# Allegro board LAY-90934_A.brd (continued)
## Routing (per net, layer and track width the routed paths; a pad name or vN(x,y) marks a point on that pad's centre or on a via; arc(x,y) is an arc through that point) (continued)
FT_NPWREN: length 2.2
  TOP w0.086: U28.60 3.46,31.02 TP136.1
FT_NSUSPEND: length 2.5
  TOP w0.086: U28.36 13.3,39.84 13.84,40.39 TP99.1
FT_ONOFF: length 7
  TOP w0.086: U13.12 46.33,71.1 46.48,71.25 46.48,72.64 46.8,72.96 48.58,72.96 v1(49.02,72.52)
  BOTTOM w0.086: U62.3 48.51,72.39 48.64,72.52 v1(49.02,72.52) R397.1
FT_OSCI: length 6.8
  TOP w0.086: U28.2 7.8,26.24 8.51,25.53 C128.1 9.02,24.26 9.02,22.23 8.04,21.25 X1.1
FT_OSCO: length 4.8
  TOP w0.086: X1.3 9.78,23.29 C134.1 8.3,26.25 U28.3
FT_POR_B: length 6.3
  TOP w0.086: U13.10 47.25,70.1 48.51,68.83 v1(48.51,67.5)
  BOTTOM w0.086: R417.1 48.26,67.25 v1(48.51,67.5) 48.51,67.5 U62.6
FT_RC_SEL: length 12.3
  TOP w0.086: R77.1 v1(38.29,67.56) ; U13.13 45.19,72.62 v1(45.21,72.64)
  BOTTOM w0.086: v1(38.29,67.56) 38.67,67.95 41.78,67.95 42.54,68.71 42.54,71.63 43.56,72.64 v1(45.21,72.64)
FT_SCL: length 111.8
  TOP w0.086: R227.2 v1(17.78,41.02) ; R255.1 v1(19.3,33.02) 18.67,33.02 18.17,33.52 U28.26 ; R155.1 v1(16,56.01) TP37.1 ; R164.2 v1(23.75,53.85) ; R45.1 v1(38.48,71.63) ; R159.2 v1(43.94,54.04)
  BOTTOM w0.086: R451.2 20.7,34.42 v1(19.3,33.02) 18.29,34.04 18.29,40.51 v1(17.78,41.02) 16.51,42.29 8.64,42.29 8,42.93 8,52.83 11.94,56.77 15.24,56.77 v1(16,56.01) 16.45,56.45 17.59,56.45 20.19,53.85 v1(23.75,53.85) 25.02,52.58 27.3,52.58 27.69,52.96 31.5,52.96 33.02,54.48 43.18,54.48 43.62,54.04 v1(43.94,54.04) 43.94,54.42 37.46,60.9 37.46,70.61 v1(38.48,71.63)
FT_SD_CD: length 127.7
  TOP w0.086: U13.16 43.69,76.32 v1(43.69,76.33)
  BOTTOM w0.086: U68.2 130.18,47.75 126.87,51.05 126.87,59.18 127.51,59.82 127.51,64.01 131.57,68.07 131.57,73.66 124.59,80.65 86.36,80.65 83.82,78.11 71.12,78.11 69.34,76.33 51.82,76.33 51.31,76.84 44.2,76.84 v1(43.69,76.33)
FT_SD_CD_EN: length 5.5
  TOP w0.086: R203.2 133.66,45.4 v1(134,45.4) U22.1
  BOTTOM w0.086: U68.4 133.84,48.4 134,48.25 134,45.77 134,45.77 v1(134,45.4)
FT_SD_PWR_EN: length 126.4
  TOP w0.086: v1(129.92,46.36) R202.2 R216.1 ; v1(51.18,74.3) v1(51.18,76.33)
  BOTTOM w0.086: U61.2 51.56,69.22 50.16,70.61 50.16,72.9 50.99,73.72 50.99,74.1 v1(51.18,74.3) ; v1(129.92,46.36) 128.08,48.2 128.08,49.47 126.62,50.93 126.62,59.31 127.25,59.94 127.25,64.14 131.32,68.2 131.32,73.53 124.46,80.39 86.49,80.39 83.95,77.85 71.25,77.85 69.47,76.07 51.43,76.07 v1(51.18,76.33)
FT_SD_PWREN: length 16.7
  TOP w0.086: v1(51.43,73.66) 51.24,73.47 44.89,73.47 44.19,72.77 U13.15
  BOTTOM w0.086: v1(51.43,73.66) 51.06,73.28 U61.6 51.06,70.74 51.69,70.1 52.2,70.1 52.77,69.53 52.77,66.99 R415.2
FT_SDA: length 111.8
  TOP w0.086: R160.2 44.7,54.48 44.7,54.48 v1(44.7,54.04) ; R156.1 v1(17.4,56.01) TP38.1 ; U28.27 18.39,34.02 18.67,34.29 ; 18.67,34.29 v1(19.3,34.29) R252.1 ; 18.67,34.29 18.44,34.52 U28.28 ; R51.1 v1(38.73,70.61) ; R228.2 v1(18.54,41.02) ; v1(23.75,53.21) 23.88,53.09 R170.2
  BOTTOM w0.086: R449.2 31.99,34.67 19.69,34.67 v1(19.3,34.29) 18.54,35.05 v1(18.54,41.02) 17.02,42.55 8.76,42.55 8.25,43.05 8.25,52.71 12.07,56.52 14.86,56.52 15.81,55.56 16.95,55.56 v1(17.4,56.01) 19.81,53.59 23.37,53.59 v1(23.75,53.21) 24.64,52.32 27.43,52.32 27.81,52.71 31.62,52.71 33.15,54.23 43.05,54.23 43.69,53.59 44.26,53.59 v1(44.7,54.04) 37.72,61.02 37.72,69.6 v1(38.73,70.61)
FT_SYS_NRST: length 4.8
  TOP w0.086: v1(46.99,72.52) 46.99,71.12 46.47,70.6 U13.11
  BOTTOM w0.086: R399.1 v1(46.99,72.52) 46.99,71.73 47.25,71.48 U62.1
FT_TEMP_NINT: length 2.5
  TOP w0.086: TP46.1 13.85,54.62 R154.2 15.5,54.1 U18.3
FT_TST0: length 29.6
  TOP w0.086: U28.21 10.77,31.02 6.98,34.8 6.98,36.45 2.79,40.64 2.79,49.28 v1(3.56,50.04) R178.1
FT_TST1: length 26.2
  TOP w0.086: R194.1 v1(3.56,47.24) 3.05,46.74 3.05,40.77 7.24,36.58 7.24,34.93 10.65,31.52 U28.22
FT_TST2: length 22.5
  TOP w0.086: R212.1 v1(3.56,44.45) 3.56,40.64 7.49,36.7 7.49,35.05 10.53,32.02 U28.23
FT_TST3: length 18.8
  TOP w0.086: U28.24 10.41,32.52 7.75,35.18 7.75,36.83 4.19,40.39 v1(4.19,41.53) R225.1
FT_USB_DN: length 29.8
  TOP w0.087: U54.C1 14.59,9.76 14.59,16.07 13.68,16.98 10.07,16.98 6.95,20.1 6.95,28.23 7.33,28.61 9.69,28.61 9.78,28.53 9.78,28.23 9.84,28.17 9.97,28.17 10.03,28.23 10.03,28.53 10.12,28.61 10.34,28.61 10.43,28.53 10.43,27.95 10.3,27.82 U28.7
FT_USB_DP: length 29.9
  TOP w0.087: U54.C2 14.37,9.76 14.37,15.98 13.59,16.76 9.98,16.76 6.73,20.01 6.73,28.32 7.24,28.83 10.43,28.83 10.64,28.62 10.64,27.98 10.8,27.82 U28.8
FTA_TCK: length 7.1
  TOP w0.086: v1(15.62,28.07) 14.99,28.07 14.8,27.88 U28.16
  BOTTOM w0.086: U65.2 19.79,29.57 18.29,28.07 v1(15.62,28.07)
FTA_TDI: length 4
  TOP w0.086: v1(17.91,28.83) 17.72,29.02 U28.17
  BOTTOM w0.086: v1(17.91,28.83) 18.67,28.83 19.81,29.97 U65.3
FTA_TDO: length 4.4
  TOP w0.086: U28.18 v1(18.67,29.52)
  BOTTOM w0.086: v1(18.67,29.52) 18.67,30.28 19.16,30.77 U65.5
FTA_TMS: length 3.6
  TOP w0.086: v1(19.43,30.37) 19.07,30.02 U28.19
  BOTTOM w0.086: v1(19.43,30.37) U65.4
FTC_RXD: length 78
  TOP w0.086: D16.C v1(11.3,39.88) 11.8,39.38 U28.39 ; v1(52.39,63.25) 51.75,63.88 49.28,63.88 49.02,64.14 42.93,64.14 38.86,60.07 37.72,60.07 35.69,62.1 v1(34.8,62.1)
  BOTTOM w0.086: v1(34.8,62.1) 34.54,61.85 26.92,61.85 22.61,57.53 11.56,57.53 6.98,52.96 6.98,42.42 8.89,40.51 10.67,40.51 v1(11.3,39.88) ; R409.1 57.4,65.66 54.61,65.66 52.39,63.44 v1(52.39,63.25)
FTC_TXD: length 78.6
  TOP w0.086: v1(35.18,61.6) 35.81,61.6 37.59,59.82 38.99,59.82 43.05,63.88 48.89,63.88 49.15,63.63 51.18,63.63 v1(52.2,62.61) ; D17.C v1(12.83,39.88) 12.3,39.35 U28.38
  BOTTOM w0.086: v1(12.83,39.88) 11.94,40.77 9.02,40.77 7.24,42.55 7.24,52.83 11.68,57.28 22.73,57.28 27.05,61.6 v1(35.18,61.6) ; R410.1 56.64,65.91 54.48,65.91 51.94,63.37 51.94,62.87 v1(52.2,62.61)
GPIO_IO00: length 57.3
  TOP w0.086: R49.2 124.59,71.51 124.59,72.14 v1(125.98,73.53) 126.24,73.53 127,74.3 J4.27 ; U1.B16 97.88,56.33 98.13,56.58 98.49,56.58 98.93,57.02 98.93,59.69 99.76,60.52 100.86,60.52 106.43,66.08 v1(106.43,71.31)
  BOTTOM w0.086: v1(106.43,71.31) 107.48,71.31 107.57,71.22 107.57,70.44 107.66,70.36 107.86,70.36 107.95,70.44 107.95,72.64 111,75.69 118.74,75.69 119.63,74.8 123.99,74.8 124.08,74.89 124.08,75.09 123.99,75.18 121.5,75.18 121.41,75.28 121.41,75.47 121.5,75.57 123.95,75.57 v1(125.98,73.53)
GPIO_IO01: length 57.1
  TOP w0.086: J4.28 127,80.14 125.73,78.87 v1(125.73,74.42) 124.07,72.77 R41.2 ; v1(106.68,71.88) 106.93,71.63 106.93,71.25 106.68,70.99 106.68,65.99 102.49,61.8 102.49,59.44 100.84,57.79 99.69,57.79 99.19,57.28 99.19,56.9 98.62,56.33 U1.B17
  BOTTOM w0.086: v1(106.68,71.88) 106.43,72.14 105.75,72.14 105.66,72.22 105.66,72.43 105.75,72.52 107.44,72.52 110.87,75.95 118.87,75.95 119.63,75.18 120.94,75.18 121.03,75.28 121.03,75.47 120.94,75.57 120.11,75.57 120.02,75.66 120.02,75.85 120.11,75.95 124.21,75.95 v1(125.73,74.42)
GPIO_IO02: length 56.6
  TOP w0.086: U1.C16 97.99,56.08 98.76,56.08 99.44,56.77 99.44,57.15 99.82,57.53 100.97,57.53 102.74,59.31 102.74,61.71 106.93,65.9 106.93,70.87 107.19,71.12 107.19,72.26 107.06,72.39 106.26,72.39 106.17,72.3 106.17,71.84 106.09,71.76 105.88,71.76 105.79,71.84 105.79,72.3 105.7,72.39 105.5,72.39 105.41,72.3 105.41,71.59 105.32,71.5 105.12,71.5 105.03,71.59 105.03,72.26 104.9,72.39 102.74,72.39 102.62,72.52 102.62,72.81 102.52,72.9 102.33,72.9 102.23,72.81 102.23,72.35 102.14,72.26 101.95,72.26 101.85,72.35 101.85,72.81 101.76,72.9 101.56,72.9 101.47,72.81 101.47,72.35 101.38,72.26 101.18,72.26 101.09,72.35 101.09,72.81 101,72.9 100.8,72.9 100.71,72.81 100.71,71.97 100.62,71.88 100.42,71.88 100.33,71.97 100.33,72.77 100.2,72.9 98.71,72.9 98.62,72.99 98.62,74.2 98.52,74.3 98.33,74.3 98.23,74.2 98.23,72.96 98.11,72.83 95.19,72.83 95,72.64 95,71.71 94.91,71.63 94.7,71.63 94.61,71.71 94.61,72.68 94.53,72.77 94.32,72.77 94.23,72.68 94.23,72.35 94.15,72.26 93.94,72.26 93.85,72.35 93.85,72.64 93.73,72.77 93.31,72.77 93.22,72.86 93.22,73.06 93.31,73.15 97.44,73.15 97.54,73.24 97.54,73.57 97.44,73.66 R23.2 96.52,73.67 J4.3
GPIO_IO03: length 57.6
  TOP w0.086: J4.5 99.06,78.36 99.19,78.49 99.99,78.49 100.08,78.57 100.08,78.78 99.99,78.87 98.38,78.87 98.3,78.95 98.3,79.16 98.38,79.25 99.99,79.25 100.08,79.33 100.08,83.31 99.95,83.44 99.66,83.44 99.57,83.53 99.57,83.73 99.66,83.82 101.13,83.82 101.22,83.73 101.22,83.53 101.13,83.44 100.58,83.44 100.46,83.31 100.46,74.3 100.33,74.17 99.19,74.17 99.06,74.04 99.06,73.67 R24.2 99.07,73.27 99.19,73.15 102.78,73.15 102.87,73.06 102.87,72.74 102.96,72.64 103.16,72.64 103.25,72.74 103.25,73.06 103.34,73.15 103.54,73.15 103.63,73.06 103.63,72.77 103.76,72.64 107.19,72.64 107.44,72.39 107.44,70.99 107.19,70.74 107.19,65.81 103,61.62 103,59.18 101.47,57.66 101.47,56.52 100.75,55.8 98.27,55.8 U1.C17
GPIO_IO04: length 61.6
  TOP w0.086: J4.7 101.6,74.42 101.73,74.3 v1(102.62,74.3) 102.74,74.3 104.14,72.9 107.31,72.9 107.7,72.52 107.7,70.87 107.44,70.61 107.44,65.72 103.25,61.53 103.25,59.06 101.73,57.53 101.73,56.39 100.92,55.58 97.99,55.58 U1.D16
  BOTTOM w0.086: v1(102.62,74.3) 102.23,74.68 81.41,74.68 80.9,74.17 77.98,74.17 77.6,73.79 75.06,73.79 R395.1
GPIO_IO05: length 54.3
  TOP w0.086: U1.D17 101.05,55.33 102.62,56.9 102.62,57.66 103.76,58.8 103.76,61.34 107.95,65.53 107.95,70.36 108.2,70.61 108.2,72.01 v1(108.46,72.26) ; v1(125.98,72.9) 126.87,73.79 127.89,73.79 128.02,73.91 128.02,74.46 128.1,74.55 128.31,74.55 128.4,74.46 128.4,73.91 128.52,73.79 129.41,73.79 129.54,73.91 129.54,76.39
  BOTTOM w0.086: v1(108.46,72.26) 108.46,72.77 111.12,75.44 118.62,75.44 119.51,74.55 123.83,74.55 123.95,74.42 123.95,73.91 124.21,73.66 125.38,73.66 125.48,73.57 125.48,73.37 125.38,73.28 124.04,73.28 123.95,73.19 123.95,72.99 124.04,72.9 v1(125.98,72.9)
GPIO_IO06: length 55.1
  TOP w0.086: U1.E16 97.99,55.08 101.18,55.08 102.87,56.77 102.87,57.53 104.01,58.67 104.01,61.23 108.2,65.42 108.2,70.23 108.46,70.49 108.46,71.25 v1(108.97,71.76) ; v1(126.75,72.77) 127.51,73.53 132.76,73.53 132.84,73.62 132.84,73.83 132.76,73.91 132.21,73.91 132.08,74.04 J4.31
  BOTTOM w0.086: v1(126.75,72.77) 126.43,72.45 124.02,72.45 123.44,73.03 123.44,74.17 123.32,74.3 119.38,74.3 118.49,75.18 111.25,75.18 108.97,72.9 v1(108.97,71.76)
GPIO_IO07: length 54.3
  TOP w0.086: J4.26 124.46,78.99 124.33,78.87 123.32,78.87 123.19,78.74 123.19,73.72 v1(122.94,73.47) ; v1(109.47,72.14) 109.47,71.63 108.71,70.87 108.71,70.36 108.46,70.1 108.46,65.33 104.27,61.14 104.27,58.55 103.12,57.4 103.12,56.64 101.31,54.83 U1.E17
  BOTTOM w0.086: v1(109.47,72.14) 109.47,73.03 111.38,74.93 118.36,74.93 119.25,74.04 122.46,74.04 122.55,73.95 122.55,73.75 122.46,73.66 119.98,73.66 119.89,73.57 119.89,73.37 119.98,73.28 122.75,73.28 v1(122.94,73.47)
GPIO_IO08: length 39.4
  TOP w0.086: v1(108.9,69.91) 108.71,69.72 108.71,65.24 104.52,61.05 104.52,58.23 v1(104.34,58.05) ; v2(96.73,51.83) U1.K14 ; U9.5 117.69,70.77 v1(117.98,70.49)
  BOTTOM w0.086: v1(117.98,70.49) 109.98,70.49 109.41,69.91 v1(108.9,69.91) ; v1(104.34,58.05) 105.28,57.11 105.28,52.58 104.14,51.44 97.13,51.44 v2(96.73,51.83)
GPIO_IO09: length 41.3
  TOP w0.086: U1.F16 97.99,54.58 101.45,54.58 104.77,57.91 104.77,60.96 108.97,65.15 108.97,69.34 109.35,69.72 109.35,70.42 v1(109.28,70.49) ; U9.7 117.8,71.57 v1(117.98,71.76)
  BOTTOM w0.086: v1(109.28,70.49) 109.54,70.74 117.51,70.74 117.6,70.83 117.6,71.03 117.51,71.12 115.03,71.12 114.94,71.21 114.94,71.41 115.03,71.5 116.33,71.5 116.46,71.63 116.46,72.3 116.55,72.39 116.75,72.39 116.84,72.3 116.84,71.59 116.93,71.5 117.13,71.5 117.22,71.59 117.22,72.3 117.31,72.39 117.52,72.39 117.6,72.3 117.6,71.88 117.73,71.76 v1(117.98,71.76)
GPIO_IO10: length 44.1
  TOP w0.086: U1.F17 101.58,54.33 105.03,57.79 105.03,60.87 109.22,65.06 109.22,65.7 109.31,65.79 109.9,65.79 109.98,65.87 109.98,66.08 109.9,66.17 109.31,66.17 109.22,66.26 109.22,66.46 109.31,66.55 109.89,66.55 109.98,66.64 109.98,66.84 109.89,66.93 109.31,66.93 109.22,67.02 109.22,67.22 109.31,67.31 109.89,67.31 109.98,67.4 109.98,67.6 109.89,67.69 109.31,67.69 109.22,67.78 109.22,67.98 109.31,68.07 109.89,68.07 109.98,68.16 109.98,68.36 109.89,68.45 109.31,68.45 109.22,68.54 109.22,68.74 109.31,68.83 109.89,68.83 109.98,68.93 109.98,69.09 109.6,69.47 109.6,70.1 109.98,70.49 v1(109.98,71.25) ; U9.10 116.28,72.59 v1(116.59,72.9)
  BOTTOM w0.086: v1(109.98,71.25) 110.11,71.37 110.11,71.8 110.2,71.88 110.4,71.88 110.49,71.8 110.49,71.08 110.58,70.99 110.78,70.99 110.87,71.08 110.87,72.56 110.96,72.64 111.17,72.64 111.25,72.56 111.25,71.12 111.38,70.99 114.49,70.99 114.62,71.12 114.62,71.76 114.74,71.88 115.99,71.88 116.08,71.97 116.08,73.28 116.2,73.41 116.46,73.41 116.59,73.28 v1(116.59,72.9)
GPIO_IO11: length 41.2
  TOP w0.086: U9.2 115.88,69.92 v1(115.95,69.85) ; U1.G16 97.99,54.08 101.71,54.08 105.28,57.66 105.28,60.78 110.24,65.74 110.24,69.79 v1(110.05,69.98)
  BOTTOM w0.086: v1(110.05,69.98) 110.36,69.66 110.36,68.93 110.45,68.83 110.65,68.83 110.74,68.93 110.74,70.14 110.84,70.23 111.03,70.23 111.12,70.14 111.12,68.93 111.22,68.83 111.41,68.83 111.51,68.93 111.51,70.14 111.6,70.23 111.8,70.23 111.89,70.14 111.89,68.93 111.98,68.83 112.18,68.83 112.27,68.93 112.27,70.14 112.36,70.23 112.56,70.23 112.65,70.14 112.65,68.93 112.74,68.83 112.94,68.83 113.03,68.93 113.03,70.14 113.12,70.23 113.32,70.23 113.41,70.14 113.41,69.43 113.5,69.34 115.44,69.34 v1(115.95,69.85)
GPIO_IO12: length 88.7
  TOP w0.086: v1(102.17,57.28) 102.17,57.59 103.5,58.93 103.5,61.47 107.7,65.66 107.7,70.49 107.95,70.74 107.95,72.64 v1(107.12,73.47) ; v1(130.05,74.04) 130.56,74.04 130.81,74.3 130.81,78.87 132.08,80.14 J4.32 ; v2(96.73,54.87) U1.F14
  BOTTOM w0.086: v1(102.17,57.28) 102.17,56.71 100.71,55.25 97.11,55.25 v2(96.73,54.87) ; R391.1 79.89,74.68 80.64,74.68 81.15,75.18 104.14,75.18 106.3,73.03 106.68,73.03 v1(107.12,73.47) 107.25,73.47 110.24,76.45 127.63,76.45 v1(130.05,74.04)
GPIO_IO13: length 93.7
  TOP w0.086: U1.G17 101.84,53.83 105.54,57.53 105.54,60.73 110.49,65.68 110.49,72.09 109.11,73.47 v1(107.82,73.47) ; J4.33 134.62,74.3 133.6,73.28 128.08,73.28 v1(127.89,73.09)
  BOTTOM w0.086: R393.1 77.34,74.94 77.85,74.42 80.77,74.42 81.28,74.93 104.01,74.93 106.17,72.77 107.12,72.77 v1(107.82,73.47) 110.55,76.2 124.97,76.2 126.75,74.42 126.75,73.41 127.06,73.09 v1(127.89,73.09)
GPIO_IO14: length 57.6
  TOP w0.086: J4.8 101.6,83.69 101.73,83.82 102.27,83.82 102.36,83.91 102.36,84.11 102.27,84.2 98.39,84.2 98.3,84.29 98.3,84.49 98.39,84.58 102.65,84.58 102.74,84.49 102.74,79.12 103,78.87 105.03,78.87 105.28,78.61 105.28,74.3 105.66,73.91 109.02,73.91 110.74,72.19 110.74,65.6 105.79,60.64 105.79,57.4 101.97,53.58 97.99,53.58 U1.H16
GPIO_IO15: length 57.7
  TOP w0.086: J4.10 104.14,83.31 104.01,83.44 103.21,83.44 103.12,83.53 103.12,83.73 103.21,83.82 105.83,83.82 105.92,83.91 105.92,84.11 105.83,84.2 103.22,84.2 103.12,84.29 103.12,84.49 103.22,84.58 106.17,84.58 106.3,84.46 106.3,83.57 106.17,83.44 105.66,83.44 105.54,83.31 105.54,79.25 105.66,79.12 106.34,79.12 106.43,79.03 106.43,78.83 106.34,78.74 105.62,78.74 105.54,78.65 105.54,74.42 105.79,74.17 109.12,74.17 111,72.29 111,65.51 106.05,60.55 106.05,57.28 102.1,53.33 U1.H17
GPIO_IO16: length 46.4
  TOP w0.086: U1.J16 97.99,53.08 102.23,53.08 106.3,57.15 106.3,60.46 111.25,65.42 111.25,73.34 v1(111.38,73.47)
  BOTTOM w0.086: U59.16 127.16,71.21 126.94,71.44 120.33,71.44 117.86,73.91 115.06,73.91 114.43,73.28 111.57,73.28 v1(111.38,73.47)
GPIO_IO17: length 59.4
  TOP w0.086: J4.11 106.68,77.6 107.95,78.87 107.95,83.69 108.2,83.95 112.52,83.95 112.78,83.69 112.78,73.5 112.68,73.41 112.49,73.41 112.39,73.31 112.39,73.12 112.49,73.03 112.81,73.03 112.9,72.93 112.9,72.74 112.81,72.64 112.49,72.64 112.39,72.55 112.39,72.35 112.49,72.26 112.81,72.26 112.9,72.17 112.9,71.97 112.81,71.88 112.49,71.88 112.39,71.79 112.39,71.59 112.49,71.5 112.81,71.5 112.9,71.41 112.9,71.21 112.81,71.12 112.23,71.12 112.14,71.03 112.14,70.83 112.23,70.74 112.81,70.74 112.9,70.65 112.9,70.45 112.81,70.36 111.85,70.36 111.76,70.27 111.76,70.07 111.85,69.98 112.56,69.98 112.65,69.89 112.65,69.68 112.57,69.6 111.85,69.6 111.76,69.5 111.76,65.24 106.81,60.29 106.81,56.9 102.49,52.58 97.48,52.58 U1.K15
GPIO_IO18: length 70.6
  TOP w0.086: v1(105.79,55.25) 107.06,56.52 107.06,60.2 112.01,65.15 112.01,68.64 113.16,69.79 113.16,73.47 v1(113.41,73.72) 113.16,73.98 113.16,84.07 112.9,84.33 106.93,84.33 106.68,84.07 J4.12 ; v2(96.73,50.87) U1.M14
  BOTTOM w0.086: v1(105.79,55.25) 105.54,54.99 105.54,52.45 104.27,51.18 97.01,51.18 96.73,50.9 v2(96.73,50.87) ; v1(113.41,73.72) 113.86,74.17 117.98,74.17 119.63,72.52 122.81,72.52 123.63,71.69 128.03,71.69 128.18,71.54 U59.1
GPIO_IO19: length 60.2
  TOP w0.086: v1(129.67,72.26) 130.18,72.77 135.64,72.77 137.16,74.3 J4.35 ; U1.J17 102.36,52.83 106.55,57.02 106.55,60.38 111.51,65.33 111.51,70.74 112.14,71.37 v1(112.14,74.04)
  BOTTOM w0.086: v1(112.14,74.04) 112.78,74.68 118.24,74.68 119.89,73.03 123.06,73.03 123.89,72.2 127.57,72.2 128.27,72.9 129.03,72.9 v1(129.67,72.26) 129.38,71.97 U59.4
GPIO_IO20: length 68.9
  TOP w0.086: U1.K16 97.99,52.08 102.75,52.08 104.9,54.23 105.79,54.23 107.57,56.01 107.57,60.02 112.52,64.97 112.52,68.39 113.66,69.53 113.66,72.39 115.7,74.42 115.7,83.31 116.46,84.07 139.06,84.07 139.7,83.44 J4.38
GPIO_IO21: length 71
  TOP w0.086: U1.K17 102.62,52.33 104.77,54.48 105.66,54.48 107.31,56.13 107.31,60.11 112.27,65.06 112.27,68.52 113.41,69.66 113.41,72.52 115.44,74.55 115.44,83.44 116.33,84.33 141.35,84.33 142.24,83.44 J4.40
HP_J_L: length 7.4
  TOP w0.254: J10.4 v1(104.93,12.85) 105.32,13.25 TVS2.2 ; TP162.1 TVS2.2 ; TVS2.2 105.32,15.8 C171.1 R335.2
HP_J_R: length 7.4
  TOP w0.254: TVS1.2 TP163.1 ; TVS1.2 111.59,13.12 v1(111.93,12.79) J10.3 ; TVS1.2 111.59,15.8 C172.2 R336.2
I2C1_SCL: length 121.4
  TOP w0.086: TP168.1 66.42,13.34 v1(66.93,13.34) R366.2 ; R94.2 102.87,65.15 v1(102.62,64.9) ; R122.1 v1(112.71,60.2) ; v1(114.43,49.91) 116.08,49.91 119.06,46.93 119.06,38.8 120.84,37.02 120.84,28 122.81,26.04 122.81,23.37 122.93,23.25 R292.2 122.83,22.76 v1(122.83,22.73) U41.8
  BOTTOM w0.086: v1(122.83,22.73) 122.45,23.11 121.41,23.11 120.02,21.72 81.91,21.72 76.96,16.76 69.72,16.76 67.44,14.48 67.44,13.84 v1(66.93,13.34) ; R419.1 102.87,65.15 v1(102.62,64.9) 105.92,61.6 112.14,61.6 112.71,61.02 v1(112.71,60.2) 112.9,60.01 112.9,51.82 114.43,50.29 v1(114.43,49.91)
I2C1_SCL_1V8: length 4.5
  TOP w0.086: U41.4 v1(122.83,19.66) R327.2 122.93,19.17 122.81,19.05 122.81,17.39 R347.2
I2C1_SDA: length 123.3
  TOP w0.086: R130.1 v1(112.46,58.93) ; TP164.1 v1(66.93,14.35) R363.2 ; U41.7 123.23,22.14 v1(123.83,22.73) 123.83,22.74 R293.2 123.95,23.25 123.83,23.37 123.83,25.4 121.16,28.07 121.16,37.21 119.38,38.99 119.38,47.12 116.14,50.36 114.05,50.36 v1(113.86,50.17) ; v1(101.85,64.77) R93.2
  BOTTOM w0.086: v1(123.83,22.73) 123.13,23.43 121.22,23.43 119.76,21.97 81.79,21.97 76.83,17.02 69.6,17.02 v1(66.93,14.35) ; v1(113.86,50.17) 112.65,51.37 112.65,58.74 v1(112.46,58.93) 112.27,59.12 112.27,61.09 112.01,61.34 105.28,61.34 v1(101.85,64.77) R420.1
I2C1_SDA_1V8: length 4.8
  TOP w0.086: R348.2 123.83,17.39 123.83,19.05 123.95,19.17 R328.2 v1(123.82,19.68) 123.23,20.28 U41.5
I2C2_SCL: length 110.3
  TOP w0.086: U1.A11 95.23,59.04 96.39,60.2 96.39,60.96 100.08,64.64 v1(100.08,64.9) 100.08,65.67 R87.2 ; R121.1 v1(108.33,60.2) ; v1(67.82,42.8) 67.18,43.43 67.18,56.13 65.66,57.66 56.26,57.66 54.1,55.5 50.93,55.5 TP42.1 49.91,54.48 R169.1
  BOTTOM w0.086: v1(67.82,42.8) 82.8,42.8 83.19,43.18 89.28,43.18 90.74,44.64 97.98,44.64 98.68,43.94 101.47,43.94 108.58,51.05 108.58,57.79 107.82,58.55 107.82,59.69 v1(108.33,60.2) 108.08,60.45 105.16,60.45 100.71,64.9 v1(100.08,64.9)
I2C2_SDA: length 113.4
  TOP w0.086: v1(68.58,42.29) 68.58,42.67 67.44,43.82 67.44,56.26 65.79,57.91 56.13,57.91 53.97,55.75 49.53,55.75 TP41.1 48.89,55.12 R168.1 ; U1.B11 95.49,56.58 95.49,58.91 96.65,60.07 96.65,60.83 100.58,64.77 v1(100.58,65.41) R88.2 ; R129.1 v1(108.33,58.93)
  BOTTOM w0.086: v1(68.58,42.29) 68.83,42.55 82.93,42.55 83.31,42.93 89.41,42.93 90.87,44.39 97.85,44.39 98.55,43.69 101.6,43.69 108.84,50.93 108.84,58.42 v1(108.33,58.93) 108.84,59.44 108.84,60.33 108.46,60.71 105.28,60.71 v1(100.58,65.41)
I2C3_SCL: length 1.3
  TOP w0.086: R41.1 v1(122.68,72.01) R40.2
I2C3_SDA: length 1.3
  TOP w0.086: R48.2 v1(122.68,70.99) R49.1
I2C4_SCL: length 39.6
  TOP w0.086: R25.2 v1(100.46,73.66) R24.1 ; R28.1 v1(64.26,72.26)
  BOTTOM w0.086: v1(100.46,73.66) 99.69,74.42 85.22,74.42 83.95,73.15 78.87,73.15 78.49,73.53 65.53,73.53 v1(64.26,72.26)
I2C4_SDA: length 30.8
  TOP w0.086: R23.1 v1(95.12,73.66) R22.2 ; v1(67.56,72.26) R31.1
  BOTTOM w0.086: v1(67.56,72.26) 68.58,73.28 78.36,73.28 78.74,72.9 84.07,72.9 85.34,74.17 94.61,74.17 v1(95.12,73.66)
I2C/I3C1_SCL: length 16.2
  TOP w0.086: v1(102.87,67.28) 102.46,67.69 101.66,67.69 101.09,67.12 101.09,64.9 96.9,60.71 96.9,59.94 95.73,58.78 U1.A12
  BOTTOM w0.086: R419.2 v1(102.87,67.28) R406.2
I2C/I3C1_SDA: length 15
  TOP w0.086: v1(101.85,67.28) 101.35,66.78 101.35,64.77 97.16,60.58 97.16,59.82 95.99,58.65 95.99,56.58 U1.B12
  BOTTOM w0.086: R407.2 v1(101.85,67.28) R420.2
I3C1_SCL: length 3.7
  TOP w0.086: TP17.1 v1(102.49,69.72) 102.23,69.98 U11.B2
  BOTTOM w0.086: R405.2 102.87,68.96 R406.1 102.87,69.34 v1(102.49,69.72)
I3C1_SDA: length 3.2
  TOP w0.086: TP16.1 v1(101.85,69.79) 101.83,69.81 U11.C2
  BOTTOM w0.086: v1(101.85,69.79) R407.1 101.85,68.96 R408.2
I.MX_SPI_CLK: length 2.5
  TOP w0.086: R351.2 v1(129.29,17.4) 129.79,17.9 U43.3
I.MX_SPI_CS: length 12.1
  TOP w0.086: v1(127.76,17.78) 129.16,17.78 129.39,18.02 U43.2 ; R324.2 v1(119.63,19.17)
  BOTTOM w0.086: v1(127.76,17.78) 126.62,18.92 119.88,18.92 v1(119.63,19.17)
I.MX_SPI_MISO: length 2.3
  TOP w0.086: R352.2 130.19,17.29 v1(130.19,18.25) U43.4
I.MX_SPI_MOSI: length 2.2
  TOP w0.086: R353.2 v1(130.81,17.46) 130.59,17.68 U43.5
ILIM_5V_VBUS: length 3.5
  TOP w0.086: U48.6 33.04,14.84 33.15,14.73 33.15,12.45 TP171.1
IOEXP_IO24: length 49.1
  TOP w0.086: J4.18 v1(114.3,83.57) ; R144.2 123.32,57.15 128.14,61.98 128.14,62.42 v1(128.59,62.87)
  BOTTOM w0.086: v1(128.59,62.87) 129.67,62.87 132.72,65.91 132.72,74.17 123.83,83.06 114.81,83.06 v1(114.3,83.57)
IOEXP_IO25: length 46.1
  TOP w0.086: R143.2 119.89,56.52 120.52,56.52 120.9,56.9 123.44,56.9 128.59,62.04 v1(128.59,62.23) ; J4.22 v1(119.38,83.57)
  BOTTOM w0.086: v1(119.38,83.57) 123.7,83.57 132.97,74.3 132.97,65.79 129.41,62.23 v1(128.59,62.23)
IOEXP_IO27: length 36
  TOP w0.086: v1(127.13,64.64) 127.13,61.34 124.71,58.93 R131.2 ; v1(110.74,73.15) 110.49,73.15 109.22,74.42 J4.13
  BOTTOM w0.086: v1(110.74,73.15) 110.87,73.03 114.55,73.03 115.19,73.66 117.73,73.66 120.9,70.49 123.32,70.49 123.57,70.74 124.33,70.74 126.75,68.33 126.75,65.02 v1(127.13,64.64)
JTAG_TCK: length 21.9
  TOP w0.086: U1.U3 91.23,46.97 88.39,44.13 88.39,43.56 TP88.1 R229.1 88.39,42.03 88.27,41.91 88.27,40.51 84.2,36.45 84.2,35.31 82.42,33.53 81.28,33.53 81.08,33.73 U27.2
JTAG_TDI: length 21
  TOP w0.086: U27.5 83.35,34.83 83.95,35.43 83.95,36.55 87.5,40.11 TP96.1 88.01,41.78 88.01,44.13 90.8,46.93 v1(90.8,47.43) ; v2(93.19,50.32) 93.21,50.33 U1.P8
  BOTTOM w0.086: v2(93.19,50.32) 93.18,50.31 93.18,50.27 92.84,49.92 92.84,49.47 v1(90.8,47.43)
JTAG_TDO: length 18.7
  TOP w0.086: U27.10 81.48,36.65 82.04,37.21 83.9,37.21 86.74,40.06 86.74,42.67 TP86.1 86.3,43.18 89.66,46.55 89.66,47.31 90.99,48.63 90.99,49.08 U1.T3
JTAG_TMS: length 19.8
  TOP w0.086: v1(90.17,47.24) 90.17,46.67 87.5,44.01 TP87.1 86.99,42.67 86.99,39.95 83.69,36.65 83.69,35.81 83.51,35.63 U27.7 ; v2(92.25,50.32) 92.26,50.33 U1.P6
  BOTTOM w0.086: v2(92.25,50.32) 91.82,49.89 91.82,49.02 90.17,47.37 v1(90.17,47.24)
JTG_TCK: length 66.7
  TOP w0.086: J7.4 v1(76.71,31.24) 76.71,32.51 78.11,33.91 80.14,33.91 80.68,34.45 U27.1
  BOTTOM w0.086: v1(76.71,31.24) 76.2,30.73 75.18,30.73 74.93,30.99 67.94,30.99 63.37,26.42 51.43,26.42 50.29,27.56 24.64,27.56 22.63,29.57 U65.10
JTG_TDI: length 69.2
  TOP w0.086: J7.8 v1(79.25,31.5) 79.25,32.13 79.24,32.13 R258.2 ; v1(82.17,33.93) 81.88,34.22 U27.4
  BOTTOM w0.086: U65.9 22.61,29.97 24.77,27.81 50.42,27.81 51.56,26.67 63.25,26.67 67.82,31.24 75.06,31.24 75.31,30.99 75.82,30.99 76.83,32 78.74,32 v1(79.25,31.5) 81.28,33.53 81.76,33.53 v1(82.17,33.93)
JTG_TDO: length 79.1
  TOP w0.086: J7.6 77.98,27.81 77.72,27.56 76.33,27.56 76.07,27.81 v1(76.07,32.51) 76.07,36.45 78.74,39.12 80.26,39.12 81.08,38.3 U27.11
  BOTTOM w0.086: U65.7 22.57,30.77 25.02,28.32 50.67,28.32 51.82,27.18 62.99,27.18 68.33,32.51 v1(76.07,32.51)
JTG_TMS: length 70.6
  TOP w0.086: v1(83.19,36.45) 82.77,36.03 U27.8 ; 75.44,29.46 v1(75.44,31.5) 75.44,31.87 75.43,31.88 R257.2
  BOTTOM w0.086: v1(83.19,36.45) 78.99,32.26 76.71,32.26 75.95,31.5 v1(75.44,31.5) 67.69,31.5 63.12,26.92 51.69,26.92 50.55,28.07 24.89,28.07 22.59,30.37 U65.8
LD_I2C_SCL: length 16.7
  TOP w0.086: U47.B1 v1(22.48,15.46) ; v1(33.66,12.95) R368.1
  BOTTOM w0.086: v1(22.48,15.46) 22.48,14.86 26.04,11.3 32,11.3 v1(33.66,12.95)
LD_I2C_SDA: length 20
  TOP w0.086: U47.C1 v1(21.34,15.86) ; R364.1 v1(33.66,13.97)
  BOTTOM w0.086: v1(21.34,15.86) 21.49,16.01 R475.1 21.97,14.99 25.91,11.05 33.66,11.05 34.16,11.56 34.16,13.46 v1(33.66,13.97)
LD_NFLT: length 3
  TOP w0.086: U48.11 31.5,17.79 R330.2 R329.1
LD_NINT: length 12.7
  TOP w0.086: R329.2 v1(30.99,19.69) ; U47.D1 v1(24.26,16.26)
  BOTTOM w0.086: v1(30.99,19.69) 27.69,19.69 v1(24.26,16.26)
LED_B: length 1.2
  BOTTOM w0.381: Q11.3 R388.2
LED_G: length 1.2
  BOTTOM w0.381: Q13.3 R390.2
LED_R: length 1.2
  BOTTOM w0.381: Q12.3 R389.2
LINE_L: length 8.9
  TOP w0.254: U40.1 112.77,19.31 v1(112.78,19.3) C166.1 ; R335.1 v1(107.57,17.4)
  BOTTOM w0.254: v1(107.57,17.4) 110.87,17.4 v1(112.78,19.3)
LINE_R: length 9.4
  TOP w0.254: R336.1 v1(110.09,18.27) ; C165.1 v1(104.14,19.3) 104.15,19.31 U40.16
  BOTTOM w0.254: v1(110.09,18.27) 109.06,19.3 v1(104.14,19.3)
LINEVDD: length 4
  TOP w0.254: U40.6 110.66,22.57 v1(109.98,23.24)
  BOTTOM w0.381: v1(109.98,23.24) C305.1 109.19,24.3 L18.1
LPD4_VDD1: length 98.6
  TOP w0.203: R181.1 v1(20.45,51.18)
  TOP w0.254: U2.T9 74.36,48.98 v2(74.36,48.91) ; v2(80.21,48.91) 80.21,48.98 U2.G9 ; v2(80.42,46.36) 80.54,46.47 U2.F12 ; U2.G4 80.24,53.66 v2(80.24,53.72) ; U2.U1 73.06,56.03 v2(73.06,56.11) ; U2.T4 73.71,53.63 v2(73.71,53.71) ; v2(73.71,46.51) 73.71,46.58 U2.U12 ; U2.F1 80.54,56.24 v2(80.51,56.26)
  L3_PWR w0.508: v1(63.63,44.96) 57.91,44.96 56.9,43.94 56.9,41.4 56.39,40.89 53.4,40.89 52.39,39.88 38.1,39.88 37.59,39.37 v1(35.05,39.37)
  BOTTOM w0.203: v1(36.32,41.02) 36.2,41.15 29.97,41.15 27.43,43.69 27.43,46.36 23.37,50.42 21.21,50.42 v1(20.45,51.18)
  BOTTOM w0.254: v2(80.42,46.36) 80.21,46.57 v2(80.21,48.91) 80.77,49.47 80.77,53.19 v2(80.24,53.72) 80.28,53.76 C205.1 80.28,54.62 80.89,55.23 C203.1 80.89,55.89 v2(80.51,56.26) ; C204.1 73.14,56.19 v2(73.06,56.11) 74.17,55 74.17,54.16 v2(73.71,53.71) 74.17,53.25 74.17,52.45 73.67,51.96 C209.1 ; C209.1 73.67,46.55 v2(73.71,46.51) ; C209.1 74.35,48.9 v2(74.36,48.91)
  BOTTOM w0.381: C202.1 73.78,46.44 v2(73.71,46.51) ; v2(80.42,46.36) 80.42,45.75 C201.1 79.83,45.15 75.25,45.15
  BOTTOM w0.508: 73.53,44.96 v1(63.63,44.96)
LPD4_VDD2: length 63.5
  TOP w0.203: R148.1 v1(52.07,56.77) ; R166.1 v1(46.61,52.53)
  TOP w0.254: U2.N12 76.31,46.58 v2(76.31,46.51) ; v2(80.21,50.51) 80.21,50.43 U2.F8 ; v2(70.46,54.51) 70.46,54.43 U2.AA3 ; U2.U5 73.07,52.19 73.07,52.17 73.06,52.17 v2(73.06,52.11) ; v2(82.81,48.91) 82.81,48.83 U2.B10 ; v2(70.46,52.11) 70.46,52.17 70.47,52.17 70.47,52.19 U2.AA5 ; v2(75.01,46.51) 75.01,46.58 U2.R12 ; U2.B5 83.46,52.18 v2(83.46,52.11) ; v2(80.21,52.17) 80.22,52.17 80.22,52.19 U2.F5 ; v2(71.76,52.11) 71.76,52.17 71.77,52.17 71.77,52.19 U2.W5 ; U2.AB4 69.82,52.99 69.82,52.97 69.81,52.97 v2(69.81,52.91) ; v2(82.81,53.71) 82.81,53.78 U2.B3 ; U2.K10 77.61,48.83 v2(77.61,48.91) ; v2(82.16,56.11) 82.16,56.03 U2.D1 ; v2(75.66,56.11) 75.66,56.03 U2.N1 ; U2.R8 75.01,50.43 v2(75.01,50.51) ; v2(77.61,46.51) 77.61,46.57 77.62,46.57 77.62,46.59 U2.K12 ; U2.R1 74.69,56.04 v2(74.8,56.16) ; U2.AA10 70.47,48.19 70.47,48.17 70.46,48.17 v2(70.46,48.11) ; U2.U8 73.06,50.43 v2(73.06,50.51) ; U2.D12 82.16,46.58 v2(82.16,46.51) ; v2(74.93,52.01) 74.69,52.25 U2.R5 ; U2.AB9 69.81,49.63 v2(69.81,49.71) ; v2(73.06,48.11) 73.06,48.17 73.07,48.17 73.07,48.19 U2.U10 ; v2(71.76,50.51) 71.76,50.43 U2.W8 ; U2.H5 79.56,52.83 v2(79.56,52.91) ; v2(78.91,46.51) 78.91,46.57 78.92,46.57 78.92,46.59 U2.H12 ; U2.H1 79.24,56.24 v2(79.26,56.26) ; U2.AA8 70.46,50.43 v2(70.46,50.51) ; v2(73.06,54.51) 73.06,54.43 U2.U3 ; U2.A4 v2(84.33,53.31) ; v2(82.16,52.19) U2.D5 ; U2.F10 80.86,48.83 v2(80.86,48.91) ; U2.W1 71.76,56.03 v2(71.76,56.11) ; U2.N10 76.31,48.18 v2(76.31,48.11) ; U2.H8 79.24,50.56 v2(79.12,50.67) ; U2.N3 75.66,54.43 v2(75.66,54.51) ; v2(71.76,46.51) 71.76,46.57 71.77,46.57 71.77,46.59 U2.W12 ; U2.A9 v2(84.33,49.31) ; v2(77.69,54.48) 77.69,54.35 U2.K3 ; U2.D8 82.16,50.43 v2(82.16,50.51) ; U2.F3 80.86,54.43 v2(80.86,54.51) ; v2(83.46,50.51) 83.46,50.43 U2.B8 ; v2(77.62,56.03) U2.K1
  BOTTOM w0.203: v1(60.2,53.47) 58.67,51.94 47.12,51.94 46.61,52.45 v1(46.61,52.53) ; v1(52.07,56.77) 52.07,56.39 53.59,54.86 60.13,54.86 61.59,53.4 61.59,52.32 v1(61.72,52.2)
  BOTTOM w0.254: v2(82.16,52.19) 82.13,52.19 81.74,52.58 C221.1 ; R210.1 79.38,56.12 79.26,56.24 v2(79.26,56.26) ; v2(83.46,50.51) 83.55,50.6 R211.2 ; R209.1 83.55,52.02 v2(83.46,52.11) ; v2(76.31,46.51) 76.34,46.48 C212.1 ; v2(82.16,46.51) 82.25,46.6 C216.1 ; C208.1 84.18,49.16 v2(84.33,49.31) ; v2(70.46,50.51) 70.47,50.52 C220.1 ; C218.1 82.38,55.89 v2(82.16,56.11) ; v2(74.93,52.01) 74.66,52.27 C210.1 ; C214.1 84.18,53.45 v2(84.33,53.31) ; v2(92.26,54.81) 92.43,54.81 C153.1 ; v2(70.46,54.51) 70.37,54.6 C219.1 ; C211.1 v2(77.61,48.91) ; v2(82.16,50.51) 82.08,50.51 C217.1 ; v2(71.76,46.51) 71.77,46.5 C222.1 ; C213.1 74.94,50.58 v2(75.01,50.51)
  BOTTOM w0.381: C206.1 75.68,54.49 v2(75.66,54.51) ; C215.1 71.88,56.22 v2(71.76,56.11) ; v2(75.66,56.11) 75.56,56.21 C207.1
  vias: v1(63.88,54.86) v1(63.88,53.47) v1(63.88,52.2) v1(64.52,54.23) v1(64.52,52.83) v1(65.15,54.86) v1(65.15,53.47) v1(65.15,52.2) v2(91.74,50.83) v2(92.26,53.83) v2(92.26,52.83) v2(92.24,51.82) v2(92.26,50.84)
LPD4_VDD2_1V1: length 20.5
  TOP w0.203: R167.1 v1(47.62,52.53) ; v1(51.69,48.13) 51.69,46.48 51.08,45.87 U23.10
  BOTTOM w0.203: v1(47.62,52.53) 47.83,52.32 58.42,52.32 59.18,53.09 v1(59.18,53.47)
  BOTTOM w0.254: v1(56.26,47.37) 54.86,47.37 54.1,48.13 v1(51.69,48.13)
LPD4_VDD2_SW: length 3.5
  TOP w0.254: U19.5 54.95,48.66 v1(54.93,48.64) 54.28,48.64 TP71.1
  BOTTOM w0.254: R435.2 54.17,49.4 v1(54.93,48.64) 55.18,48.39 R437.2
M1_SCL: length 1.9
  BOTTOM w0.086: U64.4 v1(33.91,34.12) 33.33,34.12 R451.1
M1_SDA: length 2.8
  BOTTOM w0.086: R449.1 35.8,35.18 U64.5
M2_32K_IN: length 164.4
  TOP w0.086: v1(125.22,23.75) 127.39,21.58 Q9.1 ; R146.1 v1(18.67,56.01) R157.1
  BOTTOM w0.086: v1(125.22,23.75) 120.9,23.75 119.38,22.23 76.07,22.23 74.17,24.13 65.91,24.13 65.15,24.89 50.93,24.89 49.66,26.16 27.05,26.16 25.53,24.64 17.02,24.64 14.35,27.31 14.35,39.88 13.21,41.02 9.14,41.02 7.49,42.67 7.49,52.71 11.81,57.02 17.65,57.02 v1(18.67,56.01)
M2_ALERT_B: length 4.4
  TOP w0.086: U41.3 122.43,19.3 R326.2 121.91,19.17 121.79,19.05 v1(121.79,17.39) R346.2
M2_ALT_B: length 3
  TOP w0.086: J8.62 123.79,14.89 v1(123.19,15.49) 122.94,15.49 R346.1
M2_I2C_SCL: length 2.6
  TOP w0.086: J8.60 v1(124.29,15.16) R347.1
M2_I2C_SDA: length 2.4
  TOP w0.086: J8.58 124.79,15.29 124.33,15.75 R348.1
M2_LED1#: length 4.3
  TOP w0.086: J8.6 137.79,14.86 137.98,15.05 v1(139.27,15.05) D27.C
M2_LED2#: length 2.5
  TOP w0.086: D26.C 135.29,16.33 J8.16
M2_LS_OE: length 11.6
  TOP w0.086: U43.12 v1(128.27,19.69) ; R314.1 R315.1 120.28,21.21 v1(120.9,21.21) U41.12
  BOTTOM w0.086: v1(128.27,19.69) 124.46,19.69 124.21,19.94 124.21,20.7 123.7,21.21 v1(120.9,21.21)
M2_NALERT: length 44.8
  TOP w0.086: U41.9 122.43,23.12 R291.2 121.91,23.25 121.79,23.37 121.79,26.67 120.52,27.94 120.52,36.83 118.74,38.61 118.74,46.61 v1(117.35,48.01) ; R119.2 v1(122.81,60.96)
  BOTTOM w0.086: v1(122.81,60.96) 121.41,59.56 121.41,58.55 116.97,54.1 116.97,48.39 v1(117.35,48.01)
M2_NDIS1: length 80.6
  TOP w0.086: R71.2 116.46,67.95 v1(116.46,68.58) ; v1(130.68,28.19) 134.62,24.26 R286.1 ; v1(124.59,22.1) 124.84,21.84 124.84,15.75 125.29,15.3 J8.56
  BOTTOM w0.086: v1(116.46,68.58) 116.71,68.83 117.35,68.83 118.24,67.95 119.13,67.95 119.57,68.39 120.33,68.39 121.16,67.56 124.08,67.56 125.22,66.42 125.22,64.14 124.84,63.75 124.84,57.53 124.21,56.9 124.21,50.67 125.73,49.15 125.73,37.72 129.92,33.53 129.92,30.99 129.54,30.61 129.54,29.34 v1(130.68,28.19) 130.68,27.31 125.48,22.1 v1(124.59,22.1)
M2_NDIS2: length 75.7
  TOP w0.086: v1(129.29,26.8) 134.62,21.46 R310.1 R316.2 ; R72.2 v1(117.22,68.39) ; v1(125.16,22.61) 125.16,15.94 125.79,15.3 J8.54
  BOTTOM w0.086: v1(125.16,22.61) 125.48,22.61 129.29,26.42 v1(129.29,26.8) 129.29,30.73 129.67,31.12 129.67,33.27 125.48,37.47 125.48,49.02 123.95,50.55 123.95,57.02 124.59,57.66 124.59,63.88 124.97,64.26 124.97,66.29 123.95,67.31 121.03,67.31 120.21,68.14 119.7,68.14 119.25,67.69 117.92,67.69 v1(117.22,68.39)
M2_PCM_CLK: length 3.6
  TOP w0.086: J8.8 137.29,14.87 137.8,15.37 138.24,15.37 v1(138.37,15.49) 138.8,15.49 R358.2
M2_PCM_IN: length 2.7
  TOP w0.086: J8.12 136.29,15.02 v1(136.9,15.62) R356.2
M2_PCM_OUT: length 2.5
  TOP w0.086: R355.2 v1(135.89,15.62) 135.79,15.53 J8.14
M2_PCM_SYNC: length 3.1
  TOP w0.086: R357.2 137.98,15.68 137.6,15.68 136.78,14.86 136.78,13.95 J8.10
M2_PWRON: length 4.6
  TOP w0.254: R286.2 R279.2 R276.2 R272.1 139.95,27.31 U32.5
M2_SAI1_RXD0: length 19.9
  TOP w0.086: U31.11 126.17,31.93 125.6,31.37 125.6,30.35 126.87,29.08 128.15,29.08 134.12,23.11 136.78,23.11 138.43,21.46 U44.9
M2_SAI1_TXC: length 19.7
  TOP w0.086: U44.7 139.23,21.68 137.03,23.88 134.37,23.88 130.18,28.07 130.18,28.96 130.81,29.59 130.81,31.12 129.19,32.73 U31.4
M2_SAI1_TXD0: length 21.9
  TOP w0.086: U44.10 138.03,21.36 136.65,22.73 133.99,22.73 128.02,28.7 126.75,28.7 125.22,30.23 125.22,32.89 125.67,33.34 U31.8
M2_SAI1_TXFS: length 18.1
  TOP w0.086: U31.1 128.87,31.53 130.43,29.97 130.43,29.59 129.79,28.96 129.79,27.94 130.75,26.99 130.75,26.99 134.25,23.5 136.91,23.5 138.83,21.57 U44.8
M2_SCL: length 2.4
  TOP w0.086: U16.4 44.05,57.32 43.94,57.21 v1(43.94,55.63) R159.1
M2_SD_CLK: length 58.1
  TOP w0.086: J8.9 137.04,4.94 137.41,4.57 137.41,3.68 TP183.1 138.18,2.41 137.54,1.78 119.51,1.78 113.66,7.62 113.66,14.67 115.06,16.07 115.06,18.92 115.7,19.56 115.7,25.78 114.17,27.31 114.17,30.39 114.09,30.48 113.88,30.48 113.79,30.39 113.79,30.06 113.71,29.97 113.5,29.97 113.41,30.06 113.41,30.35 113.12,30.64 U29.16
M2_SD_CMD: length 59.2
  TOP w0.086: J8.11 136.54,4.81 TP181.1 R387.2 137.29,3.3 137.67,2.92 137.67,2.41 137.29,2.03 119.63,2.03 113.92,7.75 113.92,14.54 116.08,16.7 116.08,18.42 115.95,18.54 115.53,18.54 115.44,18.63 115.44,18.84 115.53,18.92 115.95,18.92 116.08,19.05 116.08,25.91 114.55,27.43 114.55,32.13 114.35,32.33 U29.3
M2_SD_DATA0: length 56.4
  TOP w0.086: J8.13 136.04,4.85 TP180.1 R386.2 135.25,3.3 134.62,2.67 119.38,2.67 114.17,7.87 114.17,14.41 116.46,16.7 116.46,26.54 116.33,26.67 115.82,26.67 114.94,27.56 114.94,29.85 115.06,29.97 115.23,29.97 115.32,30.06 115.32,30.27 115.23,30.35 115.03,30.35 114.94,30.44 114.94,30.64 115.03,30.73 115.35,30.73 115.44,30.83 115.44,31.02 115.35,31.12 115.06,31.12 114.94,31.24 114.94,32.64 115.03,32.73 U30.9
M2_SD_DATA1: length 52
  TOP w0.086: U30.12 115.99,31.53 115.82,31.37 115.82,30.1 115.32,29.59 115.32,27.69 115.95,27.05 116.59,27.05 116.84,26.8 116.84,16.7 114.43,14.29 114.43,8 119.51,2.92 134.37,2.92 135.13,3.68 135.13,4.83 135.54,5.24 J8.15
M2_SD_DATA2: length 50.3
  TOP w0.086: J8.17 135.04,5.25 134.75,4.95 134.75,3.81 134.11,3.18 119.63,3.18 114.68,8.13 114.68,14.16 117.22,16.7 117.22,26.8 117.47,27.05 118.11,27.05 118.62,27.56 118.62,29.59 117.57,30.64 U30.16
M2_SD_DATA3: length 52.4
  TOP w0.086: J8.19 134.54,5.26 134.37,5.08 134.37,3.94 133.86,3.43 119.76,3.43 114.94,8.26 114.94,14.03 117.6,16.7 117.6,20.32 117.73,20.45 118.15,20.45 118.24,20.54 118.24,20.74 118.15,20.83 117.69,20.83 117.6,20.92 117.6,21.12 117.69,21.21 118.15,21.21 118.24,21.3 118.24,26.67 119,27.43 119,32.13 118.8,32.33 U30.3
M2_SD_NWAKE: length 41.3
  TOP w0.086: U41.2 v1(122.03,19.79) 121.41,19.17 R325.2 ; J8.21 134.04,5.39 133.48,4.83 TP179.1 132.72,3.68 119.89,3.68 115.19,8.38 115.19,13.91 118.11,16.83 v1(118.11,19.69)
  BOTTOM w0.086: v1(122.03,19.79) 122.02,19.79 121.54,19.3 120.14,19.3 119.76,19.69 v1(118.11,19.69)
M2_SDA: length 1.4
  TOP w0.086: R160.1 44.7,55.5 45.25,56.05 U16.5
M2_UART_NWAKE: length 55.5
  TOP w0.086: v1(124.84,33.4) 124.84,28.26 126.3,26.8 128.65,26.8 133.35,22.1 133.35,16.38 133.6,16.14 R354.2 134.29,15.95 J8.20 ; v1(122.11,56.01) 121.86,55.75 117.6,55.75 R140.2
  BOTTOM w0.086: v1(124.84,33.4) 124.21,34.04 124.21,48.39 121.92,50.67 121.92,55.82 v1(122.11,56.01)
M2_USB_DN: length 4.4
  TOP w0.087: J8.5 138.04,5.47 138.19,5.32 138.19,4 138.79,3.4 139.36,3.4 139.45,3.31 TP184.1
M2_USB_DP: length 4.4
  TOP w0.087: TP182.1 139.45,3.7 139.36,3.61 138.88,3.61 138.4,4.09 138.4,5.32 138.54,5.47 J8.3
M3_SCL: length 1.8
  TOP w0.086: U17.4 25.69,54.02 v1(25.53,53.85) R164.1
M3_SDA: length 2.7
  TOP w0.086: U17.5 27.53,53.09 v1(27.05,53.09) R170.1
M4_SCL: length 2.4
  TOP w0.086: R227.1 v1(17.78,43.18) 17.78,44.25 17.89,44.36 U21.4
M4_SDA: length 1.4
  TOP w0.086: U21.5 19.09,43.09 18.54,42.55 R228.1
MIC/CAN_SEL: length 41.5
  TOP w0.086: U10.15 97.4,70.79 v1(97.16,70.55) ; 131.19,66.55 R89.1 129.29,66.55 129.29,66.93 129.03,67.18 127,67.18 126.49,67.69 v1(120.02,67.69) R74.2
  BOTTOM w0.086: v1(97.16,70.55) 99.76,73.15 101.98,73.15 105.16,69.98 105.16,68.07 106.43,66.8 111.89,66.8 112.52,67.44 119.76,67.44 v1(120.02,67.69)
MX_POR_B: length 16.8
  TOP w0.086: R55.2 89.43,69.71 R56.2 89.67,69.47 C36.1 TP21.1 91.57,68.2 92.46,67.31 92.46,61.47 92.99,60.94 92.99,56.94 92.99,56.94 92.99,56.73 92.99,56.73 92.99,56.58 U1.B7
NVCC_1V8: length 89.8
  TOP w0.203: R197.1 v1(25.91,46.86)
  TOP w0.254: U1.L6 92.73,52.37 v2(92.73,52.38) ; v2(94.23,51.33) U1.L9 U1.L11
  L2_GND w0.254: v2(94.23,51.33) 93.17,52.4 92.76,52.4 v2(92.73,52.38)
  L3_PWR w0.635: v1(64.01,43.94) 63.82,44.13 58.36,44.13 57.72,43.5 57.72,40.96 56.83,40.07 53.78,40.07 52.77,39.05 38.54,39.05 37.59,38.1 v1(36.7,38.1)
  BOTTOM w0.203: v1(25.91,46.86) 25.4,46.36 25.4,41.4 28.45,38.35 36.45,38.35 v1(36.7,38.1)
  BOTTOM w0.254: v2(92.73,52.38) 92.71,52.35 C115.1 ; C116.1 94.25,51.32 v2(94.23,51.33)
  BOTTOM w0.508: v2(94.23,51.33) 93.73,50.83 93.73,48.78
  BOTTOM w0.635: v1(64.01,43.94) 81.66,43.94 82.17,44.45 88.01,44.45 90.11,46.55 91.5,46.55 93.73,48.78
NVCC_3V3: length 88.2
  TOP w0.203: TP58.1 41.72,52.01 41.72,53.53 34.54,60.71 29.47,60.71 R125.1
  TOP w0.254: U1.H13 96.23,52.88 v2(96.21,52.86) 96.23,52.83 U1.K13
  L3_PWR w0.635: v1(43.31,51.56) 47.75,51.56 48.39,52.2 54.36,52.2 58.04,55.88 58.04,64.64 58.67,65.28 69.34,65.28 70.1,66.04 81.79,66.04 82.68,65.15 84.33,65.15 85.22,66.04 98.42,66.04 99.31,65.15 v1(99.31,64.52)
NVCC_BBSM_1P8: length 43.5
  TOP w0.203: U23.38 49.39,41.04 49.66,40.77 C90.1 ; TP119.1 47.5,35.69 v1(46.61,35.69)
  TOP w0.254: R190.1 v1(45.72,49.27) ; C90.1 49.28,40.01 49.02,39.75 v1(49.02,38.35)
  TOP w0.381: v1(49.02,38.35) TP111.1 R243.1 TP119.1
  BOTTOM w0.203: R448.1 v1(46.61,35.69)
  BOTTOM w0.254: v1(45.72,49.27) 46.22,48.77 54.1,48.77 54.99,47.88 56.52,47.88 57.02,47.37 57.02,39.62 56.26,38.86 53.72,38.86 52.32,37.47 49.4,37.47 49.02,37.85 v1(49.02,38.35)
NVCC_BBSM_1V8: length 151.5
  TOP w0.254: R6.1 v1(54.23,77.34) ; R57.1 v1(91.57,70.99) ; U1.E10 95.2,54.83 v2(95.23,54.86) ; R9.1 v1(57.28,77.34) ; R56.1 v1(89.53,70.99)
  TOP w0.381: v1(85.85,68.01) 86.49,67.37 R92.1 86.11,66.8 85.85,66.54 85.85,64.14 v1(85.47,63.75) ; J1.1 J1.2 59.82,78.14 v1(59.82,77.34) 60.96,76.2 v1(60.96,70.36) ; TP118.1 45.72,36.13 v1(46.1,36.51) R243.2 ; v1(68.45,39.5) 68.45,41.28 66.67,43.05 66.67,56.01 v1(65.79,56.9)
  L3_PWR w0.381: v1(93.85,61.91) 93.85,56.77 94.73,55.89 94.73,55.13 95,54.86 v2(95.23,54.86)
  BOTTOM w0.203: R440.1 42.67,36.07 45.66,36.07 v1(46.1,36.51)
  BOTTOM w0.254: C101.1 95.51,54.86 v2(95.23,54.86) ; v1(59.82,77.34) v1(57.28,77.34) 56.77,77.85 54.74,77.85 v1(54.23,77.34)
  BOTTOM w0.381: v1(93.85,61.91) 92.84,62.93 92.84,69.72 v1(91.57,70.99) 91.06,70.49 90.04,70.49 v1(89.53,70.99) 86.55,68.01 v1(85.85,68.01) 84.26,69.6 61.72,69.6 v1(60.96,70.36) ; v1(46.1,36.51) 46.67,36.51 47.5,35.69 52.83,35.69 54.36,37.21 59.18,37.21 61.59,39.62 68.33,39.62 v1(68.45,39.5) ; v1(65.79,56.9) 72.64,63.75 v1(85.47,63.75)
NVCC_SD: length 39.1
  TOP w0.203: R213.1 25.78,44.32 25.78,42.04 32.77,35.05 48.39,35.05 TP120.1 ; U23.39 49.79,41.15 50.67,40.26 50.67,40.1 C91.1
  TOP w0.254: v1(51.43,38.35) 51.43,39.79 51.25,39.97 C91.1
  TOP w0.381: v1(51.43,38.35) TP112.1 51.43,36.45 50.8,35.81 R250.1 TP120.1
  BOTTOM w0.381: v1(51.43,38.35) 51.05,38.74 C257.1
NVCC_SD2: length 98.3
  TOP w0.203: R220.1 25.4,43.68 25.4,41.88 32.61,34.67 48.77,34.67
  TOP w0.254: v1(128.27,58.67) 126.62,58.67 123.06,55.12 111.89,55.12 110.17,53.4 v1(106.05,53.4) ; R173.1 v1(128.27,51.82) ; R218.1 C77.1 ; R151.1 v1(128.27,56.13) ; v2(96.2,50.86) 96.17,50.83 U1.N12
  TOP w0.381: TP127.1 50.55,34.16 50.67,34.29 ; U22.5 139.26,45.4 C77.1 v1(139.32,46.1)
  BOTTOM w0.203: v1(128.27,51.82) 127.89,52.2 127.89,55.75 v1(128.27,56.13)
  BOTTOM w0.254: v1(106.05,53.4) 106.05,51.69 104.52,50.17 98.04,50.17 97.64,49.76 v4(97.16,49.76) 96.55,49.15 R312.1 95.71,49.19 C129.1 95.71,50.61 95.96,50.86 v2(96.2,50.86) ; v1(128.27,58.67) v1(128.27,56.13)
  BOTTOM w0.381: v1(128.27,56.13) 131.06,56.13 139.32,47.88 v1(139.32,46.1)
  vias: v1(49.02,33.27) v1(50.8,33.27)
ODT_CA_A: length 1.5
  TOP w0.086: v2(80.21,55.31) 79.89,54.98 U2.G2
  BOTTOM w0.086: R210.2 79.84,54.93 v2(80.21,55.31)
ONOFF: length 107
  TOP w0.086: v2(95.23,55.37) 95.2,55.33 U1.D10 ; C9.1 v1(14.61,78.23) R10.2 ; v1(49.28,65.09) 49.72,64.64 v1(56.64,64.64) ; v1(87.12,64.9) TP27.1 R92.2
  BOTTOM w0.086: v2(95.23,55.37) 95.23,55.38 94.87,55.74 94.87,56.77 87.12,64.52 v1(87.12,64.9) 85.47,66.55 70.48,66.55 69.6,67.44 60.83,67.44 58.04,64.64 v1(56.64,64.64) ; v1(14.61,78.23) 16.26,78.23 19.94,74.55 44.45,74.55 45.97,73.03 45.97,63.12 46.35,62.74 48.39,62.74 49.28,63.63 v1(49.28,65.09) R416.2
PD_BYPASS: length 1.6
  TOP w0.086: C169.2 70.85,16.62 U49.4
PD_DBG_ACC: length 1.9
  TOP w0.086: U49.9 69.11,12.59 TP170.1
PD_EN_SINK: length 1.8
  TOP w0.086: R339.1 v1(71.88,16.13) 71.65,15.89 U49.2
PD_EN_SRC: length 2.1
  TOP w0.086: TP165.1 74.53,14.24 U49.16
PD_FRS_EN: length 2.8
  TOP w0.086: U49.1 72.05,15.4 72.14,15.49 TP157.1
PD_ILIM_5V_VBUS: length 2.6
  TOP w0.086: U49.6 69.32,14.24 68.07,15.49 TP156.1
PD_LD_NFLT: length 1.7
  TOP w0.086: R376.1 v1(71.12,11.68) 71.25,11.81 U49.11
PD_USB_CC1: length 7.5
  TOP w0.086: U49.13 72.05,12.03 v1(72.26,11.81) ; U52.A2 75.69,9.14 v1(75.82,9.02)
  BOTTOM w0.086: v1(75.82,9.02) 75.82,10.99 74.99,11.81 v1(72.26,11.81)
PD_USB_CC2: length 6.9
  TOP w0.086: U52.B2 U52.C2 U52.C1 v1(76.71,10.49) ; U49.14 73.04,13.44 v1(73.28,13.21)
  BOTTOM w0.086: v1(76.71,10.49) 73.99,13.21 v1(73.28,13.21)
PD_VBUS_PG: length 11.8
  TOP w0.086: v1(65.91,11.56) 65.79,11.43 R374.2 66.89,10.92 Q10.1 ; U45.A2 67.94,18.78 TP153.1 67.94,16.26 v1(68.96,15.24)
  BOTTOM w0.086: v1(68.96,15.24) 68.96,14.61 v1(65.91,11.56)
PDM_CLK: length 23.9
  TOP w0.086: U1.A16 97.73,57.22 98.42,57.91 98.42,59.94 101.73,63.25 102.91,63.25 105.92,66.26 105.92,67.69 105.41,68.2 101.6,68.2 101.09,68.71 101.09,70.23 101.41,70.55 101.41,71.04 101.26,71.19 U10.7
PDM_CLK_1V8: length 256.1
  TOP w0.086: v1(2.29,12.83) R371.1 ; U66.4 81.01,82.54 80.26,81.78 R3.1 75.69,84.2 51.31,84.2 v1(51.18,84.07) ; v1(1.52,79.38) R4.1 ; v1(80.26,11.68) R372.1
  BOTTOM w0.086: v1(80.26,11.68) 81.15,10.79 81.15,5.21 78.74,2.79 68.83,2.79 67.82,1.78 52.2,1.78 51.31,2.67 8.25,2.67 5.71,5.21 5.71,6.35 6.86,7.49 6.86,9.27 5.08,11.05 4.06,11.05 v1(2.29,12.83) 1.65,13.46 1.65,50.67 10.03,59.06 10.03,66.8 5.84,70.99 5.84,73.79 4.83,74.8 2.92,74.8 1.52,76.2 v1(1.52,79.38) 5.97,83.82 50.93,83.82 v1(51.18,84.07)
PDM_D0: length 90.6
  TOP w0.086: R379.2 v1(1.52,7.49) ; R384.2 v1(79.38,2.79) ; U53.2 v1(6.1,9.4)
  BOTTOM w0.086: v1(79.38,2.79) 79.12,2.54 68.96,2.54 67.94,1.52 52.07,1.52 51.18,2.41 8.13,2.41 5.46,5.08 5.46,6.48 6.6,7.62 6.6,8.89 v1(6.1,9.4) 5.59,9.91 1.9,9.91 1.52,9.53 v1(1.52,7.49)
PDM_D1: length 84.7
  TOP w0.086: v1(51.75,83.76) 51.94,83.95 75.44,83.95 77.47,81.92 77.47,78.35 R13.2 ; U3.2 v1(6.1,79.88) ; v1(2.16,77.72) R12.2
  BOTTOM w0.086: v1(2.16,77.72) 4.32,79.88 v1(6.1,79.88) 9.78,83.57 51.56,83.57 v1(51.75,83.76)
PDM_DATA0: length 15.1
  TOP w0.086: U10.2 98.86,69.65 98.68,69.47 98.68,64.9 98.17,64.39 98.17,63.5 95.88,61.21 95.88,60.45 94.73,59.3 U1.A10
PDM_DATA1: length 16.6
  TOP w0.086: U10.5 100.37,70.39 100.46,70.31 100.46,69.34 98.93,67.82 98.93,64.77 98.42,64.26 98.42,63.37 96.14,61.09 96.14,60.33 94.99,59.17 94.99,56.58 U1.B10
PERST: length 2.4
  TOP w0.086: J8.52 126.29,15.57 R480.1
PMIC_32K_OUT: length 36.6
  TOP w0.086: R157.2 21.85,51.44 v1(22.23,51.44) ; v1(49.31,47.5) 48.99,47.17 U23.14
  BOTTOM w0.086: v1(22.23,51.44) 23.62,51.44 24.38,50.67 31.5,50.67 33.78,52.96 41.27,52.96 45.78,48.45 48.07,48.45 49.02,47.5 v1(49.31,47.5)
PMIC_NINT: length 119.2
  TOP w0.086: v1(71.63,70.49) v1(71.63,68.14) ; R117.2 v1(122.81,61.98) R116.2 ; U23.19 46.99,46.99 46.48,47.5 44.96,47.5 44.7,47.75 44.7,49.15 44.45,49.4 44.45,50.36 45.94,51.84 48.03,51.84 48.39,52.2 48.39,55.75 48.64,56.01 53.59,56.01 v1(53.85,56.26)
  BOTTOM w0.086: v1(71.63,70.49) 72.01,70.87 72.52,70.87 72.9,70.49 79.25,70.49 79.88,71.12 84.96,71.12 86.23,72.39 91.57,72.39 92.2,71.76 93.85,71.76 94.23,71.37 94.23,69.47 94.87,68.83 96.01,68.83 96.39,68.45 99.57,68.45 101.85,70.74 103.25,70.74 104.39,69.6 104.39,67.18 103.57,66.36 103.57,66.1 104.77,64.9 119.25,64.9 120.4,66.04 123.32,66.04 123.7,65.66 123.7,64.9 123.32,64.52 123.32,62.48 v1(122.81,61.98) ; v1(71.63,68.14) 71.44,67.95 60.58,67.95 58.04,65.41 54.74,65.41 52.83,63.5 52.83,57.28 v1(53.85,56.26)
PMIC_ON_REQ: length 223.1
  TOP w0.086: v1(4.7,44.45) 5.59,44.45 6.97,45.83 Q5.1 v1(9.02,45.83) ; v1(50.16,49.4) 50.16,49.14 R191.1 ; U1.A7 93.23,61.07 92.72,61.58 92.72,67.93 TP22.1 R58.1 91.67,69.71 R57.2 91.18,69.6 91.06,69.72 91.06,71.37 90.68,71.76 86.23,71.76 84.45,69.98 84.45,65.91 82.17,63.63 73.41,63.63 69.47,59.69 58.93,59.69 57.78,60.83 50.55,60.83 47.75,63.63 43.18,63.63 40.39,60.83 40.39,56.52 42.42,54.48 v1(42.42,52.58)
  BOTTOM w0.086: R476.1 52.58,6.99 40.26,6.99 37.08,3.81 25.91,3.81 12.95,16.76 9.52,16.76 6.6,19.69 4.57,19.69 2.35,21.91 2.35,42.1 v1(4.7,44.45) ; v1(50.16,49.4) 46.23,49.4 45.9,49.73 44.93,49.73 43.9,50.76 43.9,51.73 43.05,52.58 v1(42.42,52.58) 41.78,53.21 33.66,53.21 31.37,50.93 24.51,50.93 23.5,51.94 19.05,51.94 16.89,49.78 11.18,49.78 9.65,48.26 9.65,46.47 v1(9.02,45.83)
PMIC_STBY_REQ: length 176.5
  TOP w0.086: v1(72.26,70.42) 72.26,62.87 69.34,59.94 59.05,59.94 57.66,61.34 v1(51.24,61.34) ; Q6.1 v1(8.89,43.04) ; R59.1 v1(93.6,69.09) 93.73,68.96 TP23.1 94.49,68.96 97.28,68.96 98.42,67.82 98.42,65.02 97.92,64.52 97.92,63.63 95.63,61.34 95.63,60.58 94.49,59.43 94.49,56.08 U1.C9 ; v1(44.7,38.23) 45.21,38.74 R237.1
  BOTTOM w0.086: v1(51.24,61.34) 51.05,61.15 51.05,54.48 51.69,53.85 51.69,53.47 51.18,52.96 42.67,52.96 42.16,53.47 33.53,53.47 31.24,51.18 24.64,51.18 23.62,52.2 18.92,52.2 16.76,50.04 11.05,50.04 8.57,47.56 8.51,47.56 8.51,43.42 v1(8.89,43.04) 9.13,42.8 17.53,42.8 22.73,37.59 40.13,37.59 40.77,38.23 v1(44.7,38.23) ; v1(72.26,70.42) 72.45,70.23 79.38,70.23 80.01,70.87 85.09,70.87 86.36,72.14 91.44,72.14 92.08,71.5 93.73,71.5 93.98,71.25 93.98,69.47 v1(93.6,69.09)
POR_B: length 213.3
  TOP w0.086: v1(88.65,70.99) R55.1 ; U23.11 50.19,46.96 50.28,47.05 50.74,47.05 51.18,47.5 51.18,53.09 v1(50.55,53.72) ; U34.2 v1(72.64,28.07) ; Q4.1 v1(8.89,48.63) 10.93,48.63 14.22,45.34 14.22,41.4 14.8,40.83 v1(15.05,40.83) ; v1(66.17,24.89) 66.17,24.13 D23.A
  BOTTOM w0.086: v1(72.64,28.07) 70.1,28.07 66.93,24.89 v1(66.17,24.89) 65.66,25.4 51.18,25.4 49.91,26.67 26.8,26.67 25.27,25.15 17.27,25.15 14.86,27.56 14.86,40.64 v1(15.05,40.83) ; v1(88.65,70.99) 88.27,70.61 80.14,70.61 79.5,69.98 61.98,69.98 60.71,71.25 60.71,74.3 60.2,74.8 48.26,74.8 48.01,74.55 R398.2 48.03,73.91 48.48,74.36 49.85,74.36 50.1,74.1 50.1,73.34 49.78,73.03 49.78,63.63 50.55,62.87 v1(50.55,53.72) 50.04,53.21 42.8,53.21 42.29,53.72 33.4,53.72 31.12,51.44 24.77,51.44 23.75,52.45 18.8,52.45 16.64,50.29 10.55,50.29 v1(8.89,48.63)
QSPIA_DATA0: length 28.7
  TOP w0.086: U30.8 116.37,34.03 v1(116.36,34.04) ; U20.5 TP62.1 123.19,52.07 121.16,52.07 v1(120.52,51.44)
  BOTTOM w0.086: v1(120.52,51.44) 120.4,51.31 120.4,50.8 120.65,50.55 120.65,38.74 120.02,38.1 120.02,35.91 119.92,35.81 119.73,35.81 119.63,35.91 119.63,36.74 119.54,36.83 119.34,36.83 119.25,36.74 119.25,35.43 119.13,35.31 117.22,35.31 116.36,34.44 v1(116.36,34.04)
QSPIA_DATA1: length 24.4
  TOP w0.086: v1(121.48,41.34) 121.28,41.53 U20.2 ; U30.11 115.75,31.93 v1(115.44,31.62)
  BOTTOM w0.086: v1(121.48,41.34) 121.54,41.28 121.54,34.13 121.45,34.04 121.25,34.04 121.16,34.13 121.16,37.88 121.07,37.97 120.87,37.97 120.78,37.88 120.78,33.4 118.87,31.5 115.57,31.5 v1(115.44,31.62)
QSPIA_DATA2: length 22.6
  TOP w0.086: U30.1 118.2,31.53 118.49,31.24 v1(118.49,30.61) ; v1(122.55,41.34) U20.3
  BOTTOM w0.086: v1(118.49,30.61) 119,30.61 123.06,34.67 123.06,40.8 122.97,40.89 122.77,40.89 122.68,40.8 122.68,37.68 122.59,37.59 122.39,37.59 122.3,37.68 122.3,41.08 v1(122.55,41.34)
QSPIA_DATA3: length 24.7
  TOP w0.086: v1(120.9,50.93) 121.28,50.55 U20.7 ; v1(119.38,32.73) U30.4
  BOTTOM w0.086: v1(119.38,32.73) 119.63,32.99 119.63,35.09 119.73,35.18 119.92,35.18 120.02,35.09 120.02,33.87 120.11,33.78 120.3,33.78 120.4,33.87 120.4,37.97 121.03,38.61 121.03,50.8 v1(120.9,50.93)
QSPIA_NSS0: length 33.5
  TOP w0.086: v1(113.98,32.73) U29.4 ; U20.1 v1(120.02,41.15) R233.2 120.71,40.51 120.72,40.51 TP98.1
  BOTTOM w0.086: v1(120.02,41.15) 119.51,40.64 119.51,40.22 119.6,40.13 119.8,40.13 119.89,40.22 119.89,40.42 119.98,40.51 120.18,40.51 120.27,40.42 120.27,38.86 119.63,38.23 119.63,37.3 119.54,37.21 119.34,37.21 119.25,37.3 119.25,37.5 119.16,37.59 118.96,37.59 118.87,37.5 118.87,35.91 118.78,35.81 118.58,35.81 118.49,35.91 118.49,36.74 118.4,36.83 118.2,36.83 118.11,36.74 118.11,36.07 117.98,35.94 115.7,35.94 115.57,35.81 115.57,33.62 115.48,33.53 115.28,33.53 115.19,33.62 115.19,35.85 115.1,35.94 114.9,35.94 114.81,35.85 114.81,32.35 114.72,32.26 114.52,32.26 114.43,32.35 114.43,35.85 114.34,35.94 114.07,35.94 113.98,35.85 v1(113.98,32.73)
